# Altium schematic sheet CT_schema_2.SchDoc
size 276 x 169 mm
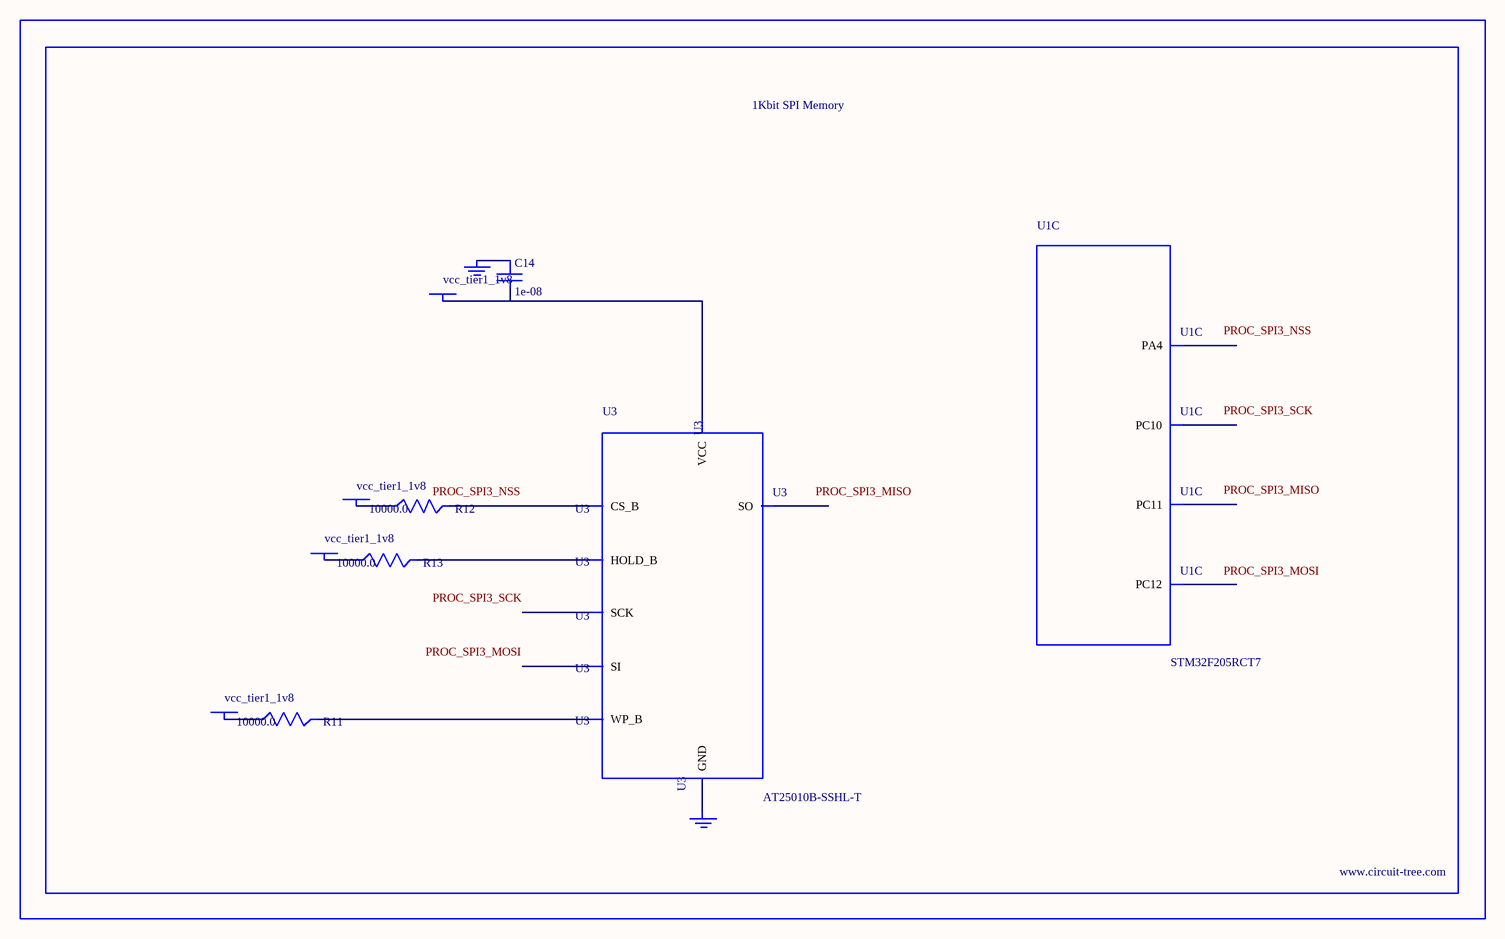
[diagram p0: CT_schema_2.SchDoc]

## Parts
BORDER1  (no value)
C14  1e-08  [C0402]
GND_INSTANCE_1_0  (no value)
GND_INSTANCE_1_1  (no value)
POWER_INSTANCE_1_0  vcc_tier1_1v8
POWER_INSTANCE_1_1  vcc_tier1_1v8
POWER_INSTANCE_1_2  vcc_tier1_1v8
POWER_INSTANCE_1_3  vcc_tier1_1v8
R11  10000.0  [R0603]
R12  10000.0  [R0603]
R13  10000.0  [R0603]
U1  STM32F205RCT7  [LQFP64]  (part C of 7)
U3  AT25010B-SSHL-T  [SOIC-8]

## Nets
NetC14_1: C14.1 GND_INSTANCE_1_0.0(GND)
NetC14_2: C14.2 POWER_INSTANCE_1_3.0(PWR) U3.8(VCC)
NetGND_INSTANCE_1_1_0: GND_INSTANCE_1_1.0(GND) U3.4(GND)
NetPOWER_INSTANCE_1_0_0: POWER_INSTANCE_1_0.0(PWR) R12.1
NetPOWER_INSTANCE_1_1_0: POWER_INSTANCE_1_1.0(PWR) R11.1
NetPOWER_INSTANCE_1_2_0: POWER_INSTANCE_1_2.0(PWR) R13.1
NetR11_2: R11.2 U3.3(WP_B)
NetR12_2: R12.2 U3.1(CS_B)
NetR13_2: R13.2 U3.7(HOLD_B)

Not connected (* = marked no-connect by the designer): U1 20(PA4) 51(PC10) 52(PC11) 53(PC12); U3 2(SO) 5(SI) 6(SCK)

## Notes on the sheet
- Labels drawn without touching a wire or pin: PROC_SPI3_MISO, PROC_SPI3_MOSI, PROC_SPI3_NSS, PROC_SPI3_SCK

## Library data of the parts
BORDER1 = BORDER_PAGE1
C14 = C0402C103K3RAC
GND_INSTANCE_1_0 GND_INSTANCE_1_1 = GND
POWER_INSTANCE_1_0-POWER_INSTANCE_1_3 = PWR
R11-R13 = RC0603JR-0710KL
